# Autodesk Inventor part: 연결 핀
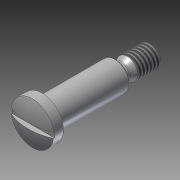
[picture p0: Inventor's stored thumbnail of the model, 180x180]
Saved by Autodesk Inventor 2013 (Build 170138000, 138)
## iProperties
Created: 2022-09
Part Number: 연결 핀
Material: 강철, 연강
Document SubType Name: Modeling
Designer: mdu-01
Density: 7.86 g/cm^3
Mass: 13.1021 g
Surface Area: 10.634 cm^2
Volume: 1.66693 cm^3
Author: mdu-01
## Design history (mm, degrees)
sketch "스케치1"
  geometry: L1 (0, 0)-(35, 0); L2 (35, 0)-(35, 3); L3 (35, 3)-(27.986, 3); L4 (25, 2.2)-(25, 4); L5 (25, 4)-(4, 4); L6 (4, 4)-(4, 6); L7 (4, 6)-(1.252, 6); L8 (0, 6)-(0, 0); L9 (27.986, 3)-(26.6, 2.2); L10 (26.6, 2.2)-(25, 2.2); A1 r 15 centre (15, 0) between (1.252, 6) and (0, 0)
  constraints: 20 end point, 4 horizontal, 4 perpendicular, 2 point on circle, 1 centre point, 1 parallel, 1 point on line
  dimensions: "d1" = 6 diameter of L3 L1; "d3" = 8 diameter of L5 L1; "d4" = 10 distance between parallel lines of L4 L2; "d5" = 21 distance between parallel lines of L6 L4; "d6" = 4 distance between parallel lines of L8 L6; "d7" = 12 diameter of L7 L1; "d8" = 4.4 diameter of L10 L1; "d9" = 1.6 distance of L9.end L4.start; "d10" = 30 deg angle of L3 L9; "d14" = 15 radius of A1
revolve "회전1" sketch "스케치1" stored, may be unused: angle "d11" = 90 deg
fillet "모깎기1" dims "d12" = 0.6
sketch "스케치2"
  geometry: L1 (0, 0.75)-(1.5, 0.75); L2 (1.5, 0.75)-(1.5, -0.75); L3 (1.5, -0.75)-(0, -0.75); L4 (0, -0.75)-(0, 0.75); 2 further points
  constraints: 8 end point, 2 parallel, 2 perpendicular, 1 coincident, 1 horizontal, 1 midpoint
  dimensions: "d15" = 1.5 distance between parallel lines of L3 L1
extrude "돌출1" cut sketch "스케치2" stored distance "d17" = 10; taper "d18" = 0 deg
feature "스레드1" dims "d20" = 10, "d21" = 0
chamfer "모따기1" distance "d22" = 0.5; stored, may be unused: second distance "d23" = 2, angle "d24" = 45 deg
node "솔리드1"
